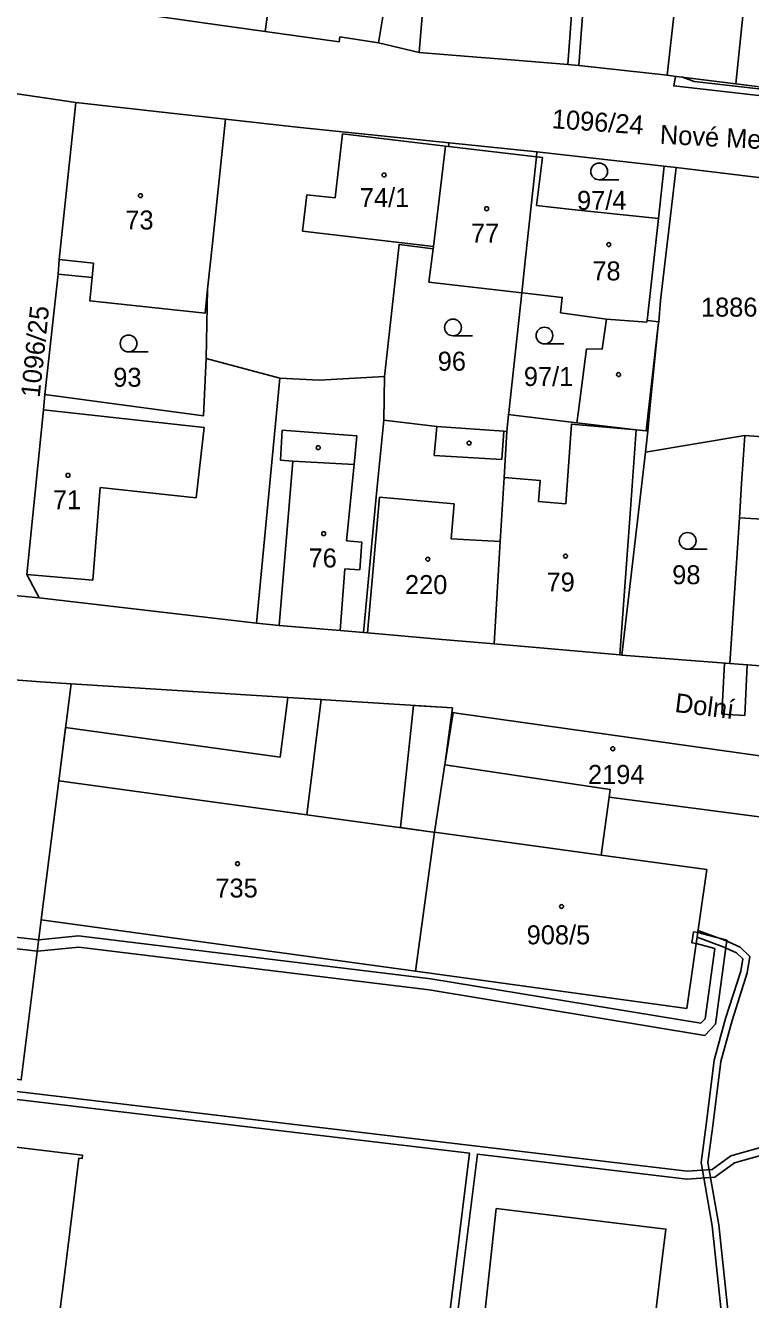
# Model space of a CAD drawing. Extents: x -680203 to -673936, y -1102717 to -1093650.
# Drawn here: x -679037.4 to -678972.5, y -1098550.5 to -1098436.4 of the extents above; entities that cross this region are included whole.
import ezdxf

# ---------------------------------------------------------------- set-up
doc = ezdxf.new("R2010")
doc.units = 0
for name, color, linetype in [('SOxx02xx_Staničení_Popis10', 7, 'Continuous'), ('SOxxxxxx_Koleje_hlavní_body_Popis10', 7, 'Continuous'), ('SOxxxxxx_Koleje_LN_parametry_Popis10', 7, 'Continuous'), ('SOxxxxxx_Koleje_param další_Popis10', 7, 'Continuous'), ('SOxxxxxx_Osa_bod_P', 7, 'Continuous'), ('SOxxxxxx_Staničení_Popis10', 7, 'Continuous'), ('x_prac', 7, 'Continuous')]:
    doc.layers.add(name, color=color, linetype=linetype)

msp = doc.modelspace()

# ---------------------------------------------------------------- linework, layer by layer
at = {"layer": 'SOxxxxxx_Koleje_hlavní_body_Popis10'}
for p, q in [((-678986.03, -1098450.26), (-678984.28, -1098450.26)), ((-678999.11, -1098464.23), (-678997.36, -1098464.23)), ((-678990.93, -1098464.96), (-678989.18, -1098464.96)), ((-679028.15, -1098465.67), (-679026.4, -1098465.67)), ((-678978.11, -1098483.34), (-678976.36, -1098483.34))]:
    msp.add_line(p, q, dxfattribs=at)
for centre in [(-678986.03, -1098449.51), (-678999.11, -1098463.48), (-679028.15, -1098464.92), (-678990.93, -1098464.21), (-678978.11, -1098482.59)]:
    msp.add_circle(centre, 0.75, dxfattribs=at)
at = {"layer": 'SOxxxxxx_Koleje_LN_parametry_Popis10'}
for points in [[(-678941.83, -1098445.51), (-678942.62, -1098445.45), (-678946.72, -1098444.88), (-678946.68, -1098444.61), (-678959.83, -1098443.28), (-678959.83, -1098443.22), (-678960.03, -1098443.22), (-678960.43, -1098443.22), (-678960.44, -1098443.4), (-678977.52, -1098441.46), (-678978.58, -1098441.08), (-678979.21, -1098441), (-678979.36, -1098441.85), (-678961.55, -1098443.87), (-678958.85, -1098443.99), (-678942.61, -1098445.62), (-678941.95, -1098446.19), (-678941.56, -1098445.74)], [(-678975.04, -1098498.1), (-678973, -1098498.21), (-678972.77, -1098493.69), (-678974.34, -1098493.57), (-678974.81, -1098493.53)], [(-679010.9, -1098496.8), (-679013.9, -1098496.61), (-679014.57, -1098501.95), (-679033.79, -1098499.3), (-679034.39, -1098504.07), (-679012.19, -1098507.11)], [(-678999.16, -1098497.54), (-679002.65, -1098497.32), (-679003.82, -1098508.26), (-679000.88, -1098508.66), (-679000.78, -1098508.67), (-678999.86, -1098502.8), (-678999.83, -1098502.64)], [(-679000.78, -1098508.67), (-678985.85, -1098510.72), (-678985.14, -1098505.54), (-678985.04, -1098504.85), (-678999.83, -1098502.64), (-678999.86, -1098502.8)]]:
    msp.add_lwpolyline(points, close=True, dxfattribs=at)
for points in [[(-678998.83, -1098552.79), (-678996.92, -1098537.49), (-678978.17, -1098539.73), (-678975.68, -1098539.57), (-678973.93, -1098538.28), (-678969.99, -1098537.17), (-678968.83, -1098528.34), (-678968.18, -1098528.41), (-678968.09, -1098527.58), (-678969.44, -1098527.58), (-678970.62, -1098536.62), (-678974.24, -1098537.64), (-678975.93, -1098538.88), (-678978.15, -1098539.03), (-678997.23, -1098536.75), (-679050.47, -1098530.43), (-679102.06, -1098524.09), (-679111.08, -1098522.81), (-679110.31, -1098515.73), (-679109.05, -1098511.06), (-679108.45, -1098505.83), (-679109.14, -1098505.73)], [(-679040.78, -1098518.8), (-679036.31, -1098519.31), (-679032.6, -1098518.97), (-679001.24, -1098522.79), (-678976.58, -1098526.86), (-678975.61, -1098525.85), (-678974.59, -1098518.35), (-678977.21, -1098517.65), (-678977.58, -1098517.59), (-678977.73, -1098518.58), (-678977.36, -1098518.64), (-678975.69, -1098519.09), (-678976.55, -1098525.39), (-678976.94, -1098525.78), (-679001.1, -1098521.79), (-679032.64, -1098517.95), (-679036.19, -1098518.32), (-679040.7, -1098517.8)], [(-678974.07, -1098555.7), (-678975.31, -1098543.82), (-678976.31, -1098538.23), (-678975.86, -1098534.96), (-678975.13, -1098529.21), (-678974.14, -1098525.53), (-678972.77, -1098521.26), (-678972.54, -1098519.8), (-678973.4, -1098518.96), (-678974.72, -1098518.38), (-678977.19, -1098517.48), (-678977.27, -1098518.06), (-678974.94, -1098518.94), (-678973.74, -1098519.46), (-678973.18, -1098520.02), (-678973.35, -1098521.12), (-678974.72, -1098525.35), (-678975.73, -1098529.09), (-678976.46, -1098534.88), (-678976.91, -1098538.25), (-678975.91, -1098543.9), (-678974.67, -1098555.76)], [(-679049.22, -1098531.29), (-678997.62, -1098537.41), (-678999.54, -1098552.87)]]:
    msp.add_lwpolyline(points, dxfattribs=at)
at = {"layer": 'SOxxxxxx_Koleje_param další_Popis10'}
for centre in [(-679005.28, -1098449.83), (-679027.09, -1098451.68), (-678996.1, -1098452.85), (-678985.17, -1098456.06), (-678984.29, -1098467.7), (-679011.17, -1098474.24), (-678997.67, -1098473.83), (-679033.57, -1098476.72), (-679010.69, -1098481.94), (-679001.37, -1098484.23), (-678989.04, -1098483.95), (-678984.81, -1098501.2), (-679018.4, -1098511.49), (-678989.39, -1098515.32)]:
    msp.add_circle(centre, 0.175, dxfattribs=at)
at = {"layer": 'SOxxxxxx_Staničení_Popis10'}
for p, q in [((-679004.24, -1098428.75), (-679005.78, -1098437.99)), ((-678987.96, -1098428.03), (-678988.84, -1098439.94)), ((-678973.79, -1098441.67), (-678972.77, -1098431.58)), ((-679009.67, -1098451.88), (-679008.99, -1098446.16)), ((-679008.99, -1098446.16), (-678999.78, -1098447.25)), ((-678999.5, -1098447.28), (-678991.65, -1098448.2)), ((-679012.58, -1098454.85), (-679012.18, -1098451.6)), ((-679012.18, -1098451.6), (-679009.67, -1098451.88)), ((-678980.73, -1098453.74), (-678981.74, -1098462.87)), ((-679000.86, -1098456.24), (-679012.58, -1098454.85)), ((-679034.36, -1098457.4), (-679031.28, -1098457.72)), ((-679031.28, -1098457.72), (-679031.41, -1098459.01)), ((-678985.36, -1098462.74), (-678981.76, -1098463.01)), ((-678981.76, -1098463.01), (-678981.74, -1098462.87)), ((-678981.74, -1098462.87), (-678980.68, -1098462.98)), ((-678980.76, -1098463.28), (-678981.82, -1098472.75)), ((-679035.77, -1098470.86), (-679021.37, -1098472.43)), ((-679021.37, -1098472.43), (-679022.09, -1098478.74)), ((-679014.56, -1098475.37), (-679014.41, -1098472.68)), ((-679014.41, -1098472.68), (-679007.73, -1098473.18)), ((-679007.73, -1098473.18), (-679007.97, -1098475.75)), ((-679000.81, -1098474.94), (-679000.57, -1098472.34)), ((-678994.55, -1098472.77), (-678994.73, -1098475.3)), ((-678982.72, -1098472.64), (-678983.22, -1098479.75)), ((-679014.66, -1098490.15), (-679013.46, -1098475.44)), ((-679013.46, -1098475.44), (-679014.56, -1098475.37)), ((-679013.46, -1098475.44), (-679007.97, -1098475.75)), ((-678994.73, -1098475.3), (-679000.81, -1098474.94)), ((-679007.97, -1098475.75), (-679008.63, -1098482.58)), ((-679030.68, -1098477.82), (-679031.36, -1098486.1)), ((-679022.09, -1098478.74), (-679030.68, -1098477.82)), ((-679006.76, -1098490.83), (-679005.7, -1098478.67)), ((-679005.7, -1098478.67), (-678999.02, -1098479.28)), ((-678999.02, -1098479.28), (-678999.29, -1098482.42)), ((-678984.19, -1098492.8), (-678983.22, -1098479.75)), ((-678973.48, -1098480.52), (-678961.78, -1098481.25)), ((-678999.29, -1098482.42), (-678994.88, -1098482.65)), ((-679008.63, -1098482.58), (-679007.27, -1098482.71)), ((-679007.27, -1098482.71), (-679007.45, -1098485.19)), ((-679031.36, -1098486.1), (-679037.24, -1098485.59)), ((-679008.8, -1098485.1), (-679009.2, -1098490.62)), ((-679007.45, -1098485.19), (-679008.8, -1098485.1)), ((-679034.39, -1098504.07), (-679000.88, -1098508.66)), ((-679000.78, -1098508.67), (-679000.88, -1098508.66))]:
    msp.add_line(p, q, dxfattribs=at)
for points in [[(-678989.02, -1098479.26), (-678988.51, -1098472.13), (-678982.72, -1098472.64)], [(-678989.02, -1098479.26), (-678991.45, -1098479.06), (-678991.31, -1098477.18), (-678994.54, -1098476.92)]]:
    msp.add_lwpolyline(points, dxfattribs=at)
at = {"layer": 'x_prac'}
for p, q in [((-678987.85, -1098440.04), (-678979.95, -1098440.9)), ((-679040.71, -1098442.18), (-679032.88, -1098443.34)), ((-679032.88, -1098443.34), (-679033.72, -1098451.5)), ((-678991.6, -1098447.77), (-678999.45, -1098446.95)), ((-678991.65, -1098448.2), (-678991.6, -1098447.77)), ((-678991.6, -1098447.77), (-678980.21, -1098449.04)), ((-678979.14, -1098449.16), (-678980.21, -1098449.04)), ((-679034.46, -1098458.7), (-679035.63, -1098469.47)), ((-679021.21, -1098466.27), (-679021.09, -1098460.04)), ((-679014.6, -1098468.01), (-679021.21, -1098466.27)), ((-679016.71, -1098489.95), (-679014.6, -1098468.01)), ((-679005.3, -1098471.77), (-679005.24, -1098467.87)), ((-678994.13, -1098471.26), (-678994.29, -1098472.79)), ((-678981.87, -1098474.66), (-678981.68, -1098472.77)), ((-678972.99, -1098473.15), (-678981.87, -1098474.66)), ((-678970.18, -1098473.36), (-678972.99, -1098473.15)), ((-678984.01, -1098492.82), (-678981.87, -1098474.66)), ((-679036.15, -1098487.68), (-679042.61, -1098487.11)), ((-679036.15, -1098487.68), (-679016.71, -1098489.95)), ((-678984.01, -1098492.82), (-678974.34, -1098493.57)), ((-679002.48, -1098521.11), (-679000.78, -1098508.67)), ((-678985.85, -1098510.72), (-679000.78, -1098508.67)), ((-679035.96, -1098516.53), (-679002.48, -1098521.11))]:
    msp.add_line(p, q, dxfattribs=at)
for points in [[(-679013.63, -1098420.13), (-679014.05, -1098423.2), (-679015.93, -1098436.98)], [(-678977.14, -1098420.43), (-678978.34, -1098426.56), (-678979.95, -1098440.9)], [(-679001.01, -1098425.26), (-679001.08, -1098426.16), (-679001.27, -1098428.38), (-679002.14, -1098438.85)], [(-678987.85, -1098440.04), (-678986.83, -1098426.31), (-679001.01, -1098425.26)], [(-679015.93, -1098436.98), (-679021.67, -1098436.17), (-679031.77, -1098434.76)], [(-679015.93, -1098436.98), (-679009.3, -1098437.91), (-679009.23, -1098437.47), (-679005.78, -1098437.99), (-679002.14, -1098438.85)], [(-679002.14, -1098438.85), (-678996.98, -1098439.27), (-678993.9, -1098439.52), (-678988.84, -1098439.94), (-678987.85, -1098440.04)], [(-678979.95, -1098440.9), (-678979.36, -1098440.98), (-678973.79, -1098441.67), (-678966.4, -1098442.59)], [(-679019.46, -1098444.83), (-679024.87, -1098444.23), (-679032.88, -1098443.34)], [(-679021.09, -1098460.04), (-679020.65, -1098455.96), (-679019.89, -1098448.84), (-679019.46, -1098444.83)], [(-679019.46, -1098444.83), (-679012.79, -1098445.57), (-678999.45, -1098446.95)], [(-678999.45, -1098446.95), (-678999.5, -1098447.28), (-678999.78, -1098447.25), (-679000.86, -1098456.24), (-679000.89, -1098456.45)], [(-678992.96, -1098460.38), (-678992.62, -1098457.25), (-678991.65, -1098448.2)], [(-678980.21, -1098449.04), (-678980.73, -1098453.74), (-678988.47, -1098452.92), (-678991.63, -1098452.55), (-678991.1, -1098448.27), (-678991.65, -1098448.2)], [(-678981.68, -1098472.77), (-678981.49, -1098470.78), (-678981.37, -1098469.53), (-678980.91, -1098464.8), (-678980.76, -1098463.28), (-678980.68, -1098462.98), (-678980.55, -1098461.07), (-678979.14, -1098449.16)], [(-678979.14, -1098449.16), (-678972.49, -1098449.96), (-678968.27, -1098450.48), (-678968.29, -1098451.2), (-678967.35, -1098451.3)], [(-679033.72, -1098451.5), (-679034.36, -1098457.4), (-679034.46, -1098458.7)], [(-679000.89, -1098456.45), (-679003.94, -1098456.05), (-679005.24, -1098467.87)], [(-679000.89, -1098456.45), (-679001.26, -1098459.42), (-678992.96, -1098460.38)], [(-679034.46, -1098458.7), (-679031.41, -1098459.01), (-679031.63, -1098461.1), (-679021.29, -1098462.2), (-679021.09, -1098460.04)], [(-678994.13, -1098471.26), (-678994.11, -1098471.1), (-678992.96, -1098460.38)], [(-678992.96, -1098460.38), (-678992.64, -1098460.42), (-678989.33, -1098460.79), (-678989.48, -1098462.17), (-678985.36, -1098462.74), (-678985.76, -1098465.41), (-678987.16, -1098465.4), (-678987.89, -1098470.94), (-678988.03, -1098472.02)], [(-679021.21, -1098466.27), (-679021.43, -1098471.38), (-679035.63, -1098469.47)], [(-679005.24, -1098467.87), (-679011.08, -1098468.21), (-679014.6, -1098468.01)], [(-679035.63, -1098469.47), (-679035.77, -1098470.86), (-679037.24, -1098485.59), (-679036.15, -1098487.68)], [(-679007.11, -1098490.8), (-679005.99, -1098478.64), (-679005.3, -1098471.77)], [(-678994.29, -1098472.79), (-678994.55, -1098472.77), (-679000.57, -1098472.34), (-679005.3, -1098471.77)], [(-678988.03, -1098472.02), (-678993.7, -1098471.32), (-678994.13, -1098471.26)], [(-678988.03, -1098472.02), (-678982.72, -1098472.64), (-678981.82, -1098472.75), (-678981.68, -1098472.77)], [(-678994.29, -1098472.79), (-678994.54, -1098476.92), (-678994.88, -1098482.65), (-678995.43, -1098491.82)], [(-678972.99, -1098473.15), (-678973.28, -1098477.46), (-678973.48, -1098480.52), (-678974.34, -1098493.57)], [(-679016.71, -1098489.95), (-679014.66, -1098490.15), (-679009.2, -1098490.62), (-679007.11, -1098490.8)], [(-679007.11, -1098490.8), (-679006.76, -1098490.83), (-679000.08, -1098491.41), (-678995.43, -1098491.82)], [(-678995.43, -1098491.82), (-678984.19, -1098492.8), (-678984.01, -1098492.82)], [(-678974.34, -1098493.57), (-678968.04, -1098494.04), (-678962.67, -1098494.41)], [(-679033.3, -1098495.39), (-679036.02, -1098495.22), (-679044.35, -1098494.59)], [(-679033.3, -1098495.39), (-679034.39, -1098504.07), (-679035.96, -1098516.53)], [(-678999.83, -1098502.64), (-678999.16, -1098497.54), (-679033.3, -1098495.39)], [(-678999.83, -1098502.64), (-678999.1, -1098497.96), (-678998.79, -1098498), (-678969.73, -1098502.11), (-678969.39, -1098502.15)], [(-679000.78, -1098508.67), (-678999.86, -1098502.8), (-678999.83, -1098502.64)], [(-678969.39, -1098502.15), (-678970.06, -1098507.26), (-678970.09, -1098507.5), (-678985.14, -1098505.54), (-678985.85, -1098510.72)], [(-678985.85, -1098510.72), (-678976.4, -1098512.01), (-678978.19, -1098524.44), (-679002.48, -1098521.11)], [(-679035.96, -1098516.53), (-679037.76, -1098530.85), (-679050.16, -1098529.28), (-679049.22, -1098523.66)], [(-679032.59, -1098537.85), (-679032.29, -1098537.88), (-679032.26, -1098537.59), (-679032.55, -1098537.55), (-679047.41, -1098535.78), (-679050.23, -1098558), (-679035.31, -1098559.84), (-679034.11, -1098550.15), (-679034.06, -1098549.76), (-679033.05, -1098541.56), (-679032.59, -1098537.85)], [(-678982.75, -1098566.46), (-678981.58, -1098556.76), (-678981.53, -1098556.36), (-678980.53, -1098548.06), (-678980.06, -1098544.21), (-678995.24, -1098542.37), (-678997.66, -1098564.68), (-678982.75, -1098566.46)]]:
    msp.add_lwpolyline(points, dxfattribs=at)

# ---------------------------------------------------------------- texts
at = {"layer": 'SOxx02xx_Staničení_Popis10'}
for s, rotation, p in [('Nové Mesto', 357, (-678980.63, -1098447.03)), ('Dolní', 353, (-678979.32, -1098497.9))]:
    msp.add_text(s, height=1.7, rotation=rotation, dxfattribs=at).set_placement(p)
at = {"layer": 'SOxxxxxx_Osa_bod_P'}
for s, rotation, p in [('1096/24', 356, (-678990.31, -1098445.64)), ('1096/25', 84, (-679036.11, -1098469.81))]:
    msp.add_text(s, height=1.7, rotation=rotation, dxfattribs=at).set_placement(p)
for s, p in [('74/1', (-679007.45, -1098452.71)), ('97/4', (-678988.01, -1098452.95)), ('73', (-679028.44, -1098454.71)), ('77', (-678997.51, -1098455.89)), ('78', (-678986.64, -1098459.27)), ('1886', (-678976.92, -1098462.51)), ('96', (-679000.48, -1098467.35)), ('93', (-679029.52, -1098468.79)), ('97/1', (-678992.77, -1098468.72)), ('71', (-679034.92, -1098479.75)), ('76', (-679012.04, -1098484.97)), ('220', (-679003.41, -1098487.35)), ('79', (-678990.74, -1098487.12)), ('98', (-678979.49, -1098486.47)), ('2194', (-678987.03, -1098504.35)), ('735', (-679020.38, -1098514.52)), ('908/5', (-678992.52, -1098518.71))]:
    msp.add_text(s, height=1.7, dxfattribs=at).set_placement(p)

doc.saveas('drawing.dxf')
